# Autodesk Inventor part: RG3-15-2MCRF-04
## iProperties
Created: 2008-09
Part Number: RG3-15-2MCRF-04
Material: 1.0037 St 37-2
Document SubType Name: Modellieren
Designer: TMT
Manufacturer: Standard
Standards Organization: Custom
Density: 7.85 g/cm^3
Mass: 26.2712 g
Surface Area: 17.5524 cm^2
Volume: 3.34665 cm^3
Author: TMT
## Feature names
1. Extrusion2
2. Rundung3 [Fillet]
3. Extrusion3
4. Extrusion4
5. Extrusion5
6. Rundung4 [Fillet]
